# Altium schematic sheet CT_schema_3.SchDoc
size 287 x 169 mm
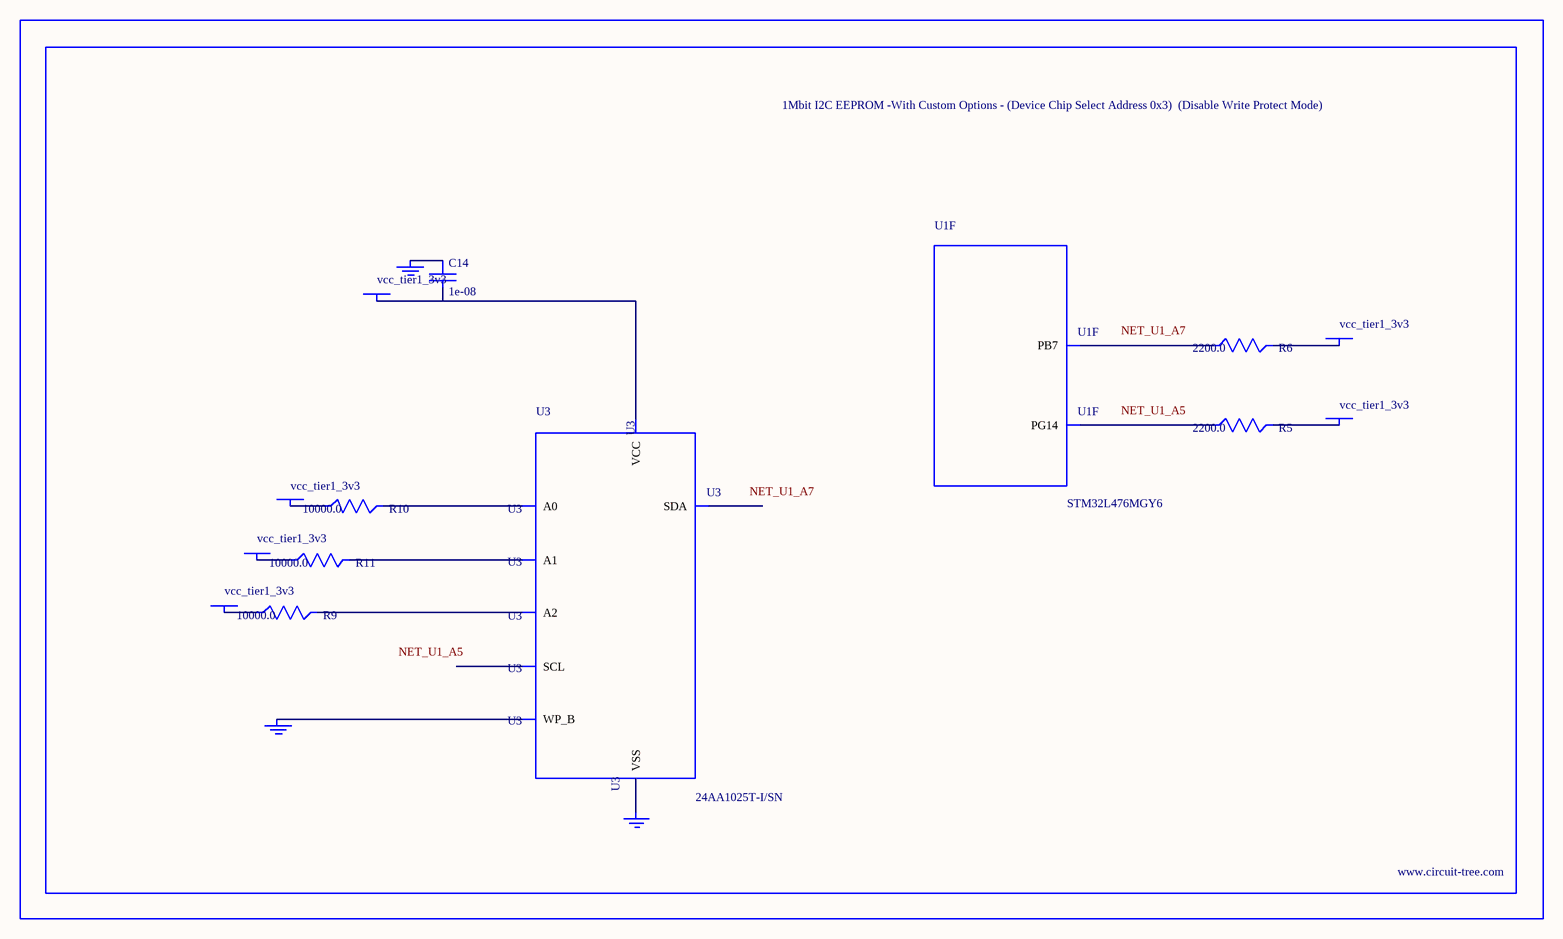
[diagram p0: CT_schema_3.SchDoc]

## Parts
BORDER2  (no value)
C14  1e-08  [C0402]
GND_INSTANCE_2_0  (no value)
GND_INSTANCE_2_1  (no value)
GND_INSTANCE_2_2  (no value)
POWER_INSTANCE_2_0  vcc_tier1_3v3
POWER_INSTANCE_2_1  vcc_tier1_3v3
POWER_INSTANCE_2_2  vcc_tier1_3v3
POWER_INSTANCE_2_3  vcc_tier1_3v3
POWER_INSTANCE_2_4  vcc_tier1_3v3
POWER_INSTANCE_2_5  vcc_tier1_3v3
R5  2200.0  [R0603]
R6  2200.0  [R0603]
R9  10000.0  [R0603]
R10  10000.0  [R0603]
R11  10000.0  [R0603]
U1  STM32L476MGY6  [WLCSP81]  (part F of 10)
U3  24AA1025T-I/SN  [SOIC-8]

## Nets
NetC14_1: C14.1 GND_INSTANCE_2_1.0(GND)
NetC14_2: C14.2 POWER_INSTANCE_2_3.0(PWR) U3.8(VCC)
NetGND_INSTANCE_2_0_0: GND_INSTANCE_2_0.0(GND) U3.7(WP_B)
NetGND_INSTANCE_2_2_0: GND_INSTANCE_2_2.0(GND) U3.4(VSS)
NetPOWER_INSTANCE_2_0_0: POWER_INSTANCE_2_0.0(PWR) R10.1
NetPOWER_INSTANCE_2_1_0: POWER_INSTANCE_2_1.0(PWR) R11.1
NetPOWER_INSTANCE_2_2_0: POWER_INSTANCE_2_2.0(PWR) R9.1
NetPOWER_INSTANCE_2_4_0: POWER_INSTANCE_2_4.0(PWR) R6.2
NetPOWER_INSTANCE_2_5_0: POWER_INSTANCE_2_5.0(PWR) R5.2
NetR5_1: R5.1 U1.A5(PG14)
NetR6_1: R6.1 U1.A7(PB7)
NetR9_2: R9.2 U3.3(A2)
NetR10_2: R10.2 U3.1(A0)
NetR11_2: R11.2 U3.2(A1)

Not connected (* = marked no-connect by the designer): U3 5(SDA) 6(SCL)

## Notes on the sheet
- Labels drawn without touching a wire or pin: NET_U1_A5, NET_U1_A7

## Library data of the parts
BORDER2 = BORDER_PAGE2
C14 = C0402C103K3RAC
GND_INSTANCE_2_0-GND_INSTANCE_2_2 = GND
POWER_INSTANCE_2_0-POWER_INSTANCE_2_5 = PWR
R5 R6 = RC0603JR-072K2L
R9-R11 = RC0603JR-0710KL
